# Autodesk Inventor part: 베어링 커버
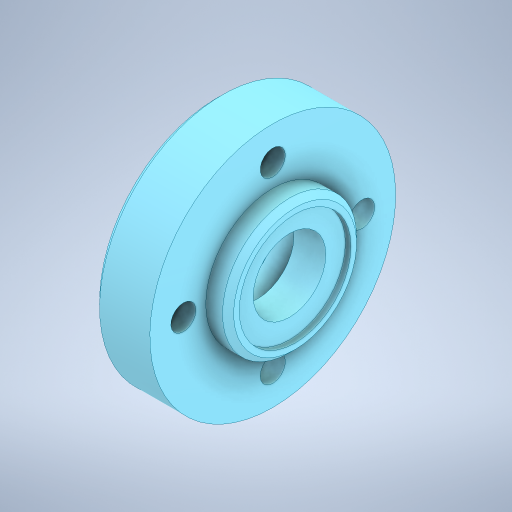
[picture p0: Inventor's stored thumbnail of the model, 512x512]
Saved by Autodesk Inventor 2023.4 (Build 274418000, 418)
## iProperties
Created: 2024-05
Part Number: 베어링 커버
Material: 강철, 연강
Document SubType Name: Modeling
Designer: EDU-001
Density: 7.85 g/cm^3
Appearance: 기본값
Author: jhkim
Sending System: Autodesk Inventor 2025
Preprocessor: ST-DEVELOPER v20
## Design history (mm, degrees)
node "베어링 커버1"
node "솔리드2"
node "솔리드1"
